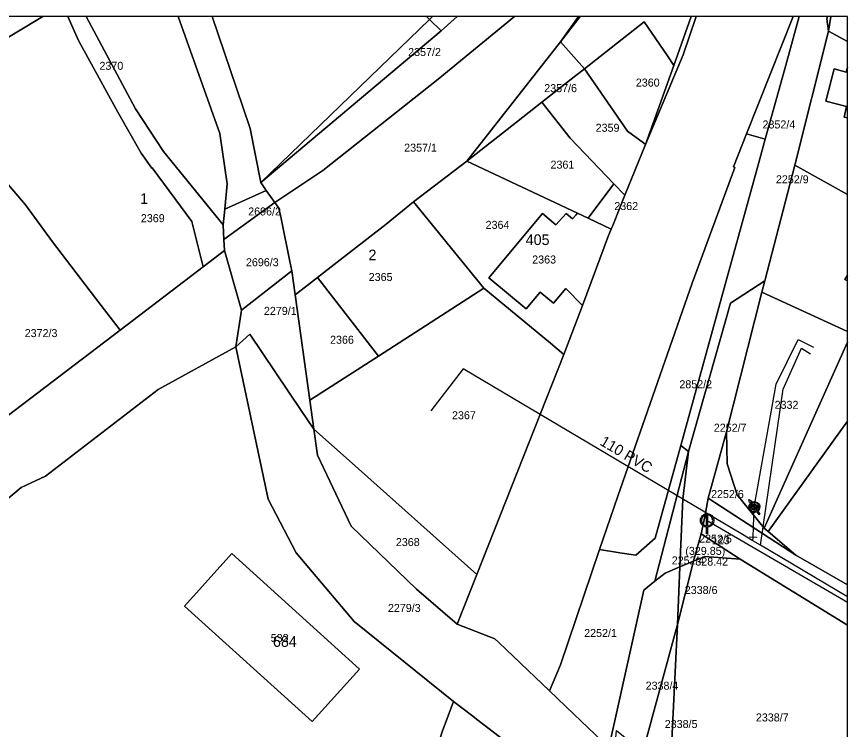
# Model space of a CAD drawing. Extents: x -561316 to -560969, y -1077679 to -1077341.
# Drawn here: x -561124.4 to -560968.7, y -1077474.3 to -1077340.8 of the extents above; entities that cross this region are included whole.
import ezdxf

# ---------------------------------------------------------------- set-up
doc = ezdxf.new("R2010")
doc.units = 0
for name, color, linetype in [('Adresní místo-text', 7, 'Continuous'), ('Armatura vodovodní', 7, 'Continuous'), ('Kanalizační přípojka', 7, 'Continuous'), ('Kanalizační stoka', 7, 'Continuous'), ('Kanalizační šachta', 7, 'Continuous'), ('Odběrné místo', 7, 'Continuous'), ('Parcela-polygon', 7, 'Continuous'), ('Parcela-text', 7, 'Continuous'), ('Popis šachty', 7, 'Continuous'), ('Vodovodní přípojka', 7, 'Continuous'), ('Vodovodní řad', 7, 'Continuous'), ('Řad vodovodní popis', 7, 'Continuous')]:
    doc.layers.add(name, color=color, linetype=linetype)

msp = doc.modelspace()

# ---------------------------------------------------------------- linework, layer by layer
at = {"layer": 'Armatura vodovodní'}
msp.add_lwpolyline([(-560986.98, -1077438.21), (-560985.73, -1077438.26), (-560985.74, -1077438.34), (-560986.99, -1077438.28), (-560986.98, -1077438.21)], dxfattribs=at)
at = {"layer": 'Kanalizační přípojka'}
msp.add_lwpolyline([(-560985, -1077439.77), (-560980.73, -1077410.59), (-560977.27, -1077402.9), (-560975.58, -1077403.92)], dxfattribs=at)
at = {"layer": 'Kanalizační stoka'}
msp.add_line((-560994.97, -1077435.15), (-560968.69, -1077450.45), dxfattribs=at)
at = {"layer": 'Kanalizační šachta'}
for points in [[(-560995.07, -1077436.19), (-560995.07, -1077434.11)], [(-560994.87, -1077434.11), (-560994.87, -1077436.19)], [(-560994.87, -1077436.4), (-560994.87, -1077437.65), (-560995.07, -1077437.65), (-560995.07, -1077436.4)]]:
    msp.add_lwpolyline(points, dxfattribs=at)
for points in [[(-560995.07, -1077436.4), (-560995.33, -1077436.38), (-560995.59, -1077436.23), (-560995.89, -1077436.07), (-560996.06, -1077435.77), (-560996.22, -1077435.47), (-560996.22, -1077435.15), (-560996.22, -1077434.82), (-560996.05, -1077434.52), (-560995.88, -1077434.22), (-560995.59, -1077434.06), (-560995.29, -1077433.9), (-560994.97, -1077433.9), (-560994.66, -1077433.9), (-560994.36, -1077434.06), (-560994.06, -1077434.22), (-560993.89, -1077434.52), (-560993.72, -1077434.82), (-560993.72, -1077435.15), (-560993.72, -1077435.47), (-560993.88, -1077435.77), (-560994.05, -1077436.07), (-560994.35, -1077436.23), (-560994.61, -1077436.38), (-560994.87, -1077436.4)], [(-560995.07, -1077434.11), (-560995.27, -1077434.13), (-560995.49, -1077434.24), (-560995.73, -1077434.38), (-560995.87, -1077434.63), (-560996.01, -1077434.88), (-560996.01, -1077435.15), (-560996.01, -1077435.42), (-560995.88, -1077435.67), (-560995.74, -1077435.91), (-560995.49, -1077436.05), (-560995.28, -1077436.17), (-560995.07, -1077436.19)], [(-560994.87, -1077436.19), (-560994.66, -1077436.17), (-560994.45, -1077436.05), (-560994.2, -1077435.91), (-560994.06, -1077435.67), (-560993.93, -1077435.42), (-560993.93, -1077435.15), (-560993.93, -1077434.88), (-560994.07, -1077434.63), (-560994.21, -1077434.38), (-560994.46, -1077434.24), (-560994.67, -1077434.13), (-560994.87, -1077434.11)]]:
    msp.add_open_spline(points, degree=3, dxfattribs=at)
at = {"layer": 'Odběrné místo'}
for points in [[(-560986.87, -1077431.71), (-560987, -1077431.81), (-560987.14, -1077431.19), (-560986.6, -1077431.51), (-560986.75, -1077431.62), (-560986.65, -1077431.78)], [(-560986.77, -1077431.86), (-560986.87, -1077431.71)], [(-560986.51, -1077432.24), (-560986.67, -1077432)], [(-560986.55, -1077431.91), (-560986.38, -1077432.16)], [(-560985.98, -1077433), (-560986.43, -1077432.34)], [(-560986.3, -1077432.27), (-560985.84, -1077432.93)], [(-560985.72, -1077433.37), (-560985.9, -1077433.12)], [(-560985.76, -1077433.04), (-560985.59, -1077433.29)], [(-560985.49, -1077433.42), (-560985.1, -1077433.99), (-560985.23, -1077434.07), (-560985.62, -1077433.51)]]:
    msp.add_lwpolyline(points, dxfattribs=at)
for points in [[(-560985.62, -1077433.51), (-560985.93, -1077433.7), (-560986.3, -1077433.63), (-560986.72, -1077433.56), (-560986.95, -1077433.22), (-560987.19, -1077432.87), (-560987.12, -1077432.46), (-560987.05, -1077432.09), (-560986.77, -1077431.86)], [(-560986.67, -1077432), (-560986.9, -1077432.19), (-560986.95, -1077432.49), (-560987.02, -1077432.83), (-560986.82, -1077433.12), (-560986.62, -1077433.41), (-560986.27, -1077433.47), (-560985.97, -1077433.52), (-560985.72, -1077433.37)], [(-560985.9, -1077433.12), (-560985.91, -1077433.12), (-560985.93, -1077433.13), (-560986.07, -1077433.17), (-560986.2, -1077433.14), (-560986.47, -1077433.09), (-560986.59, -1077432.93), (-560986.71, -1077432.76), (-560986.68, -1077432.53), (-560986.65, -1077432.39), (-560986.56, -1077432.28), (-560986.54, -1077432.26), (-560986.51, -1077432.24)], [(-560986.65, -1077431.78), (-560986.33, -1077431.58), (-560985.95, -1077431.65), (-560985.54, -1077431.72), (-560985.3, -1077432.06), (-560985.06, -1077432.4), (-560985.14, -1077432.82), (-560985.2, -1077433.19), (-560985.49, -1077433.42)], [(-560986.43, -1077432.34), (-560986.45, -1077432.36), (-560986.47, -1077432.38), (-560986.54, -1077432.45), (-560986.55, -1077432.56), (-560986.58, -1077432.7), (-560986.5, -1077432.83), (-560986.42, -1077432.95), (-560986.18, -1077433), (-560986.07, -1077433.02), (-560985.98, -1077433)], [(-560985.59, -1077433.29), (-560985.36, -1077433.09), (-560985.3, -1077432.79), (-560985.24, -1077432.44), (-560985.44, -1077432.16), (-560985.64, -1077431.87), (-560985.98, -1077431.81), (-560986.29, -1077431.76), (-560986.55, -1077431.91)], [(-560986.38, -1077432.16), (-560986.36, -1077432.15), (-560986.33, -1077432.14), (-560986.19, -1077432.1), (-560986.04, -1077432.13), (-560985.87, -1077432.16), (-560985.76, -1077432.24), (-560985.64, -1077432.33), (-560985.6, -1077432.46), (-560985.56, -1077432.59), (-560985.58, -1077432.73), (-560985.61, -1077432.88), (-560985.7, -1077432.98), (-560985.73, -1077433.02), (-560985.76, -1077433.04)], [(-560985.84, -1077432.93), (-560985.73, -1077432.85), (-560985.7, -1077432.71), (-560985.67, -1077432.55), (-560985.77, -1077432.43), (-560985.86, -1077432.31), (-560986.06, -1077432.27), (-560986.19, -1077432.25), (-560986.3, -1077432.27), (-560986.3, -1077432.27), (-560986.3, -1077432.27)]]:
    msp.add_open_spline(points, degree=3, dxfattribs=at)
at = {"layer": 'Parcela-polygon'}
for p, q in [((-561119.43, -1077340.8), (-561125.97, -1077340.8)), ((-561114.76, -1077340.8), (-561119.43, -1077340.8)), ((-561111.34, -1077340.8), (-561114.76, -1077340.8)), ((-561094.11, -1077340.8), (-561111.34, -1077340.8)), ((-561087.73, -1077340.8), (-561094.11, -1077340.8)), ((-561047.52, -1077340.8), (-561087.73, -1077340.8)), ((-561046.42, -1077340.8), (-561047.52, -1077340.8)), ((-561041.79, -1077340.8), (-561046.42, -1077340.8)), ((-561031.05, -1077340.8), (-561041.79, -1077340.8)), ((-561019.06, -1077340.8), (-561031.05, -1077340.8)), ((-561018.75, -1077340.8), (-561019.06, -1077340.8)), ((-560997.95, -1077340.8), (-561018.75, -1077340.8)), ((-560997.03, -1077340.8), (-560997.95, -1077340.8)), ((-560978.83, -1077340.8), (-560997.03, -1077340.8)), ((-560977.73, -1077340.8), (-560978.83, -1077340.8)), ((-560972.44, -1077340.8), (-560977.73, -1077340.8)), ((-560971.76, -1077340.8), (-560972.44, -1077340.8)), ((-560968.69, -1077341.31), (-560968.69, -1077341.17)), ((-560968.69, -1077345.47), (-560968.69, -1077341.31)), ((-560968.69, -1077350.26), (-560968.69, -1077345.47)), ((-560968.69, -1077359.77), (-560968.69, -1077350.26)), ((-560968.69, -1077374.12), (-560968.69, -1077359.77)), ((-560968.69, -1077389.22), (-560968.69, -1077374.12)), ((-560968.69, -1077390.3), (-560968.69, -1077389.22)), ((-560968.69, -1077399.77), (-560968.69, -1077390.3)), ((-560968.69, -1077401.73), (-560968.69, -1077399.77)), ((-560968.69, -1077416.55), (-560968.69, -1077401.73)), ((-560968.69, -1077447.23), (-560968.69, -1077416.55)), ((-560968.69, -1077454.77), (-560968.69, -1077447.23)), ((-560968.69, -1077494.47), (-560968.69, -1077454.77))]:
    msp.add_line(p, q, dxfattribs=at)
for points in [[(-561119.43, -1077340.8), (-561128.95, -1077346.48), (-561129.16, -1077368.47), (-561126.69, -1077371.36), (-561122.71, -1077376.02), (-561117.62, -1077382.95), (-561109.74, -1077393.26), (-561104.98, -1077399.49), (-561089.39, -1077387.63), (-561091.5, -1077379.14), (-561098.94, -1077369.12), (-561099.03, -1077369.17), (-561101.03, -1077366.35), (-561105.36, -1077358.71), (-561112.78, -1077345.3), (-561114.76, -1077340.8)], [(-561125.97, -1077340.8), (-561128.95, -1077346.48), (-561119.43, -1077340.8)], [(-561114.76, -1077340.8), (-561112.78, -1077345.3), (-561105.36, -1077358.71), (-561101.03, -1077366.35), (-561099.03, -1077369.17), (-561098.94, -1077369.12), (-561091.5, -1077379.14), (-561089.39, -1077387.63), (-561085.41, -1077384.6), (-561085.5, -1077382.55), (-561085.62, -1077379.76), (-561096.82, -1077366.03), (-561102.07, -1077358.07), (-561111.34, -1077340.8)], [(-561111.34, -1077340.8), (-561102.07, -1077358.07), (-561096.82, -1077366.03), (-561085.62, -1077379.76), (-561085.35, -1077376.88), (-561084.91, -1077372.14), (-561086.29, -1077362.67), (-561094.11, -1077340.8)], [(-561094.11, -1077340.8), (-561086.29, -1077362.67), (-561084.91, -1077372.14), (-561085.35, -1077376.88), (-561077.57, -1077373.33), (-561078.62, -1077371.84), (-561080.58, -1077361.77), (-561081.97, -1077357.7), (-561087.73, -1077340.8)], [(-561087.73, -1077340.8), (-561081.97, -1077357.7), (-561080.58, -1077361.77), (-561078.62, -1077371.84), (-561046.97, -1077341.34), (-561047.52, -1077340.8)], [(-561041.79, -1077340.8), (-561044.78, -1077343.48), (-561078.62, -1077371.84), (-561077.57, -1077373.33), (-561075.94, -1077375.61), (-561066.97, -1077369.6), (-561045.36, -1077352.52), (-561031.05, -1077340.8)], [(-561031.05, -1077340.8), (-561045.36, -1077352.52), (-561066.97, -1077369.6), (-561075.94, -1077375.61), (-561075.22, -1077376.64), (-561074.81, -1077378.6), (-561073.15, -1077386.66), (-561072.79, -1077388.42), (-561072.16, -1077392.88), (-561067.97, -1077389.63), (-561064.83, -1077387.2), (-561055.1, -1077379.64), (-561049.99, -1077375.45), (-561039.97, -1077367.88), (-561022.46, -1077345.5), (-561019.06, -1077340.8)], [(-561047.52, -1077340.8), (-561046.97, -1077341.34), (-561046.55, -1077340.93), (-561046.42, -1077340.8)], [(-561046.42, -1077340.8), (-561046.55, -1077340.93), (-561046.97, -1077341.34), (-561044.78, -1077343.48), (-561041.79, -1077340.8)], [(-560997.03, -1077340.8), (-560999.44, -1077347.94), (-561006.51, -1077364.73), (-561010.37, -1077374.26), (-561012.54, -1077379.61), (-561012.94, -1077380.59), (-561013.42, -1077381.77), (-561018.34, -1077394.88), (-561021.79, -1077404.06), (-561038.11, -1077445.26), (-561041.8, -1077454.56), (-561034.74, -1077457.28), (-561034.02, -1077457.97), (-561024.53, -1077467.03), (-561022.46, -1077462.15), (-561015.12, -1077440.58), (-561011.71, -1077430.57), (-560997.76, -1077390.7), (-560989.77, -1077369.06), (-560990.03, -1077368.91), (-560987.57, -1077362.74), (-560978.83, -1077340.8)], [(-561018.75, -1077340.8), (-561022.46, -1077345.5), (-561017.93, -1077350.55), (-561006.76, -1077341.79), (-561002.42, -1077348.16), (-561001.21, -1077349.92), (-560997.95, -1077340.8)], [(-561019.06, -1077340.8), (-561022.46, -1077345.5), (-561018.75, -1077340.8)], [(-560997.95, -1077340.8), (-561001.21, -1077349.92), (-561004.22, -1077358.32), (-561006.51, -1077364.73), (-560999.44, -1077347.94), (-560997.03, -1077340.8)], [(-560977.73, -1077340.8), (-560980.43, -1077350.55), (-560984.08, -1077363.76), (-560985.29, -1077368.14), (-560991.09, -1077389.15), (-560999.92, -1077421.13), (-560998.49, -1077422.25), (-560990.56, -1077394.45), (-560984.15, -1077390.27), (-560978.54, -1077368.63), (-560972.22, -1077343.5), (-560972.51, -1077341.19), (-560972.44, -1077340.8)], [(-560978.83, -1077340.8), (-560987.57, -1077362.74), (-560984.08, -1077363.76), (-560980.43, -1077350.55), (-560977.73, -1077340.8)], [(-560972.44, -1077340.8), (-560972.51, -1077341.19), (-560972.22, -1077343.5), (-560971.76, -1077340.8)], [(-560971.76, -1077340.8), (-560972.22, -1077343.5), (-560968.69, -1077345.47)], [(-560968.69, -1077341.17), (-560968.69, -1077340.8), (-560971.76, -1077340.8)], [(-560968.69, -1077341.17), (-560968.75, -1077341.28), (-560968.69, -1077341.31)], [(-560968.69, -1077341.31), (-560968.75, -1077341.28), (-560968.69, -1077341.17)], [(-560968.69, -1077345.47), (-560972.22, -1077343.5), (-560978.54, -1077368.63), (-560968.69, -1077374.12)], [(-560968.69, -1077350.26), (-560968.92, -1077351.17), (-560971.19, -1077350.59), (-560972.74, -1077356.63), (-560968.85, -1077357.62), (-560969.28, -1077359.62), (-560968.69, -1077359.77)], [(-560968.69, -1077359.77), (-560969.28, -1077359.62), (-560968.85, -1077357.62), (-560972.74, -1077356.63), (-560971.19, -1077350.59), (-560968.92, -1077351.17), (-560968.69, -1077350.26)], [(-560968.69, -1077374.12), (-560978.54, -1077368.63), (-560984.15, -1077390.27), (-560984.71, -1077392.42), (-560968.69, -1077399.77)], [(-561141.46, -1077444.02), (-561123.47, -1077428.97), (-561118.92, -1077426.82), (-561097.85, -1077410.62), (-561083.3, -1077402.66), (-561082.24, -1077395.75), (-561082.73, -1077394.02), (-561085.16, -1077385.46), (-561085.41, -1077384.6), (-561089.39, -1077387.63), (-561104.98, -1077399.49), (-561136.14, -1077423.19)], [(-560968.69, -1077390.3), (-560969.15, -1077390.04), (-560968.69, -1077389.22)], [(-560968.69, -1077389.22), (-560969.15, -1077390.04), (-560968.69, -1077390.3)], [(-560968.69, -1077399.77), (-560984.71, -1077392.42), (-560991.33, -1077418.53), (-560991.23, -1077424.52), (-560989.34, -1077430.33), (-560984.3, -1077436.58), (-560968.69, -1077401.73)], [(-560968.69, -1077401.73), (-560984.3, -1077436.58), (-560983.54, -1077437.22), (-560968.69, -1077416.55)], [(-561091.55, -1077679.32), (-561089.7, -1077665.29), (-561074.75, -1077568.98), (-561063.6, -1077534.48), (-561053.67, -1077503.25), (-561050.47, -1077493.22), (-561048.31, -1077486.41), (-561044.6, -1077474.75), (-561042.48, -1077469.05), (-561061.08, -1077454.04), (-561071.96, -1077441.19), (-561077.2, -1077431.15), (-561083.3, -1077402.66), (-561097.85, -1077410.62), (-561118.92, -1077426.82), (-561123.47, -1077428.97), (-561141.46, -1077444.02)], [(-560968.69, -1077416.55), (-560983.54, -1077437.22), (-560978.33, -1077441.62), (-560968.69, -1077447.23)], [(-560968.69, -1077447.23), (-560978.33, -1077441.62), (-560994.78, -1077430.99), (-560995.41, -1077434.44), (-560996.11, -1077437.68), (-560988.77, -1077442.39), (-560968.69, -1077454.77)], [(-561084.02, -1077441.36), (-561060.11, -1077463.02), (-561069, -1077472.82), (-561092.91, -1077451.18), (-561084.02, -1077441.36)], [(-560968.69, -1077454.77), (-560988.77, -1077442.39), (-560995.41, -1077441.87), (-560997.54, -1077442.76), (-561000.5, -1077454.6), (-561001.87, -1077482.65), (-560982.23, -1077498.52), (-560972.64, -1077506.26), (-560968.69, -1077494.47)]]:
    msp.add_lwpolyline(points, dxfattribs=at)
for points in [[(-561046.97, -1077341.34), (-561078.62, -1077371.84), (-561044.78, -1077343.48)], [(-561017.93, -1077350.55), (-561009.88, -1077362.22), (-561006.88, -1077364.43), (-561006.51, -1077364.73), (-561004.22, -1077358.32), (-561001.21, -1077349.92), (-561002.42, -1077348.16), (-561006.76, -1077341.79)], [(-561022.46, -1077345.5), (-561039.97, -1077367.88), (-561030.7, -1077360.56), (-561025.91, -1077356.81), (-561020.45, -1077352.53), (-561017.93, -1077350.55)], [(-561009.88, -1077362.22), (-561017.93, -1077350.55), (-561020.45, -1077352.53), (-561025.91, -1077356.81), (-561020.64, -1077363.57), (-561012.45, -1077372.09), (-561010.37, -1077374.26), (-561006.51, -1077364.73), (-561006.88, -1077364.43)], [(-561020.64, -1077363.57), (-561025.91, -1077356.81), (-561030.7, -1077360.56), (-561039.97, -1077367.88), (-561019.28, -1077377.61), (-561017.29, -1077378.55), (-561012.45, -1077372.09)], [(-560990.03, -1077368.91), (-560989.77, -1077369.06), (-560997.76, -1077390.7), (-561011.71, -1077430.57), (-561015.12, -1077440.58), (-561011.3, -1077441.2), (-561008.32, -1077441.67), (-561004.7, -1077438.43), (-560999.92, -1077421.13), (-560991.09, -1077389.15), (-560985.29, -1077368.14), (-560984.08, -1077363.76), (-560987.57, -1077362.74)], [(-561035.88, -1077389.73), (-561025.84, -1077377.68), (-561023.31, -1077379.79), (-561021.37, -1077377.65), (-561020.18, -1077378.69), (-561019.57, -1077377.96), (-561019.28, -1077377.61), (-561039.97, -1077367.88), (-561049.99, -1077375.45), (-561036.79, -1077391.63), (-561024.33, -1077401.95), (-561021.79, -1077404.06), (-561018.34, -1077394.88), (-561021.46, -1077391.68), (-561023.74, -1077394.46), (-561026.23, -1077392.37), (-561028.9, -1077395.54)], [(-561148.69, -1077436.73), (-561136.14, -1077423.19), (-561104.98, -1077399.49), (-561109.74, -1077393.26), (-561117.62, -1077382.95), (-561122.71, -1077376.02), (-561126.69, -1077371.36)], [(-561012.45, -1077372.09), (-561017.29, -1077378.55), (-561012.94, -1077380.59), (-561012.54, -1077379.61), (-561010.37, -1077374.26)], [(-561077.57, -1077373.33), (-561085.35, -1077376.88), (-561085.62, -1077379.76), (-561085.5, -1077382.55), (-561075.94, -1077375.61)], [(-561074.81, -1077378.6), (-561075.22, -1077376.64), (-561075.94, -1077375.61), (-561085.5, -1077382.55), (-561085.41, -1077384.6), (-561085.16, -1077385.46), (-561082.73, -1077394.02), (-561082.24, -1077395.75), (-561072.79, -1077388.42), (-561073.15, -1077386.66)], [(-561067.97, -1077389.63), (-561061.48, -1077397.99), (-561056.55, -1077404.35), (-561036.79, -1077391.63), (-561049.99, -1077375.45), (-561055.1, -1077379.64), (-561064.83, -1077387.2)], [(-561025.84, -1077377.68), (-561035.88, -1077389.73), (-561028.9, -1077395.54), (-561026.23, -1077392.37), (-561023.74, -1077394.46), (-561021.46, -1077391.68), (-561018.34, -1077394.88), (-561013.42, -1077381.77), (-561012.94, -1077380.59), (-561017.29, -1077378.55), (-561019.28, -1077377.61), (-561019.57, -1077377.96), (-561020.18, -1077378.69), (-561021.37, -1077377.65), (-561023.31, -1077379.79)], [(-561072.79, -1077388.42), (-561082.24, -1077395.75), (-561083.3, -1077402.66), (-561080.63, -1077400.23), (-561071.01, -1077414.57), (-561068.64, -1077418.05), (-561069.4, -1077412.62), (-561072.16, -1077392.88)], [(-561072.16, -1077392.88), (-561069.4, -1077412.62), (-561056.55, -1077404.35), (-561061.48, -1077397.99), (-561067.97, -1077389.63)], [(-560990.56, -1077394.45), (-560998.49, -1077422.25), (-560999.52, -1077431.13), (-561000.11, -1077443.84), (-560997.54, -1077442.76), (-560996.11, -1077437.68), (-560995.41, -1077434.44), (-560994.78, -1077430.99), (-560991.33, -1077418.53), (-560984.71, -1077392.42), (-560984.15, -1077390.27)], [(-561024.33, -1077401.95), (-561036.79, -1077391.63), (-561056.55, -1077404.35), (-561069.4, -1077412.62), (-561068.64, -1077418.05), (-561062.05, -1077423.93), (-561038.11, -1077445.26), (-561021.79, -1077404.06)], [(-561049.4, -1077448.02), (-561061.67, -1077436.19), (-561067.96, -1077422.91), (-561068.64, -1077418.05), (-561071.01, -1077414.57), (-561080.63, -1077400.23), (-561083.3, -1077402.66), (-561077.2, -1077431.15), (-561071.96, -1077441.19), (-561061.08, -1077454.04), (-561042.48, -1077469.05), (-561038.9, -1077471.78), (-561038.17, -1077472.34), (-561027.8, -1077480.27), (-561023.49, -1077483.56), (-561015.97, -1077489.32), (-561013.39, -1077477.66), (-561019.96, -1077471.39), (-561024.53, -1077467.03), (-561034.02, -1077457.97), (-561034.74, -1077457.28), (-561041.8, -1077454.56)], [(-561068.64, -1077418.05), (-561067.96, -1077422.91), (-561061.67, -1077436.19), (-561049.4, -1077448.02), (-561041.8, -1077454.56), (-561038.11, -1077445.26), (-561062.05, -1077423.93)], [(-560994.78, -1077430.99), (-560978.33, -1077441.62), (-560983.54, -1077437.22), (-560984.3, -1077436.58), (-560989.34, -1077430.33), (-560991.23, -1077424.52), (-560991.33, -1077418.53)], [(-560999.92, -1077421.13), (-561004.7, -1077438.43), (-561008.32, -1077441.67), (-561011.3, -1077441.2), (-561015.12, -1077440.58), (-561022.46, -1077462.15), (-561024.53, -1077467.03), (-561019.96, -1077471.39), (-561013.39, -1077477.66), (-561011.59, -1077469.52), (-561006.86, -1077448.2), (-561004.74, -1077446.51), (-560998.49, -1077422.25)], [(-561004.74, -1077446.51), (-561002.84, -1077444.99), (-561000.11, -1077443.84), (-560999.52, -1077431.13), (-560998.49, -1077422.25)], [(-560996.11, -1077437.68), (-560997.54, -1077442.76), (-560995.41, -1077441.87), (-560988.77, -1077442.39)], [(-561092.91, -1077451.18), (-561069, -1077472.82), (-561060.11, -1077463.02), (-561084.02, -1077441.36)], [(-561000.5, -1077454.6), (-560997.54, -1077442.76), (-561000.11, -1077443.84)], [(-561002.84, -1077444.99), (-561004.74, -1077446.51), (-561006.86, -1077448.2), (-561011.59, -1077469.52), (-561013.39, -1077477.66), (-561012.31, -1077478.48), (-561011.96, -1077474.5), (-561007.03, -1077478.49), (-561000.5, -1077454.6), (-561000.11, -1077443.84)], [(-561007.03, -1077478.49), (-561001.87, -1077482.65), (-561000.5, -1077454.6)], [(-561042.48, -1077469.05), (-561044.6, -1077474.75), (-561048.31, -1077486.41), (-561043.17, -1077489.63), (-561034.56, -1077495.01), (-561029.82, -1077484.67), (-561027.8, -1077480.27), (-561038.17, -1077472.34), (-561038.9, -1077471.78)]]:
    msp.add_lwpolyline(points, close=True, dxfattribs=at)
at = {"layer": 'Vodovodní přípojka'}
for points in [[(-560986.13, -1077432.64), (-560982.02, -1077409.61), (-560977.88, -1077401.24), (-560975.01, -1077402.68)], [(-560986.39, -1077438.94), (-560986.36, -1077438.27), (-560986.13, -1077432.64)]]:
    msp.add_lwpolyline(points, dxfattribs=at)
at = {"layer": 'Vodovodní řad'}
msp.add_lwpolyline([(-560968.69, -1077449.44), (-560985, -1077439.77), (-560986.39, -1077438.94), (-560988.35, -1077437.78), (-561040.68, -1077406.77), (-561046.77, -1077414.63)], dxfattribs=at)

# ---------------------------------------------------------------- texts
at = {"layer": 'Adresní místo-text'}
for s, p in [('1', (-561101.19, -1077375.87)), ('405', (-561028.96, -1077383.57)), ('2', (-561058.42, -1077386.43)), ('684', (-561076.32, -1077458.81))]:
    msp.add_text(s, height=2, dxfattribs=at).set_placement(p)
at = {"layer": 'Parcela-text'}
for s, p in [('2357/2', (-561050.99, -1077348.18)), ('2370', (-561108.83, -1077350.76)), ('2357/6', (-561025.49, -1077354.94)), ('2360', (-561008.33, -1077353.9)), ('2359', (-561015.86, -1077362.36)), ('2852/4', (-560984.59, -1077361.74)), ('2357/1', (-561051.73, -1077366.09)), ('2361', (-561024.31, -1077369.27)), ('2252/9', (-560982.08, -1077372.01)), ('2696/2', (-561080.96, -1077378.03)), ('2362', (-561012.36, -1077377.02)), ('2369', (-561101.07, -1077379.29)), ('2364', (-561036.47, -1077380.54)), ('2696/3', (-561081.38, -1077387.54)), ('2363', (-561027.74, -1077387.03)), ('2365', (-561058.38, -1077390.3)), ('2279/1', (-561078.01, -1077396.65)), ('2372/3', (-561122.84, -1077400.81)), ('2366', (-561065.62, -1077402.06)), ('2852/2', (-561000.17, -1077410.39)), ('2332', (-560982.32, -1077414.24)), ('2367', (-561042.77, -1077416.19)), ('2252/7', (-560993.72, -1077418.53)), ('2252/6', (-560994.23, -1077430.95)), ('2368', (-561053.29, -1077439.94)), ('2252/5', (-560996.47, -1077439.31)), ('2252/4', (-561001.6, -1077443.38)), ('2338/6', (-560999.16, -1077448.92)), ('2279/3', (-561054.78, -1077452.28)), ('2252/1', (-561018.01, -1077456.97)), ('532', (-561076.74, -1077457.9)), ('2338/4', (-561006.49, -1077466.83)), ('2338/7', (-560985.83, -1077472.78)), ('2338/5', (-561002.91, -1077474.01))]:
    msp.add_text(s, height=1.5, dxfattribs=at).set_placement(p)
at = {"layer": 'Popis šachty'}
for s, p in [('123', (-560994.08, -1077439.59)), ('(329.85)', (-560999.05, -1077441.59)), ('328.42', (-560997.18, -1077443.59))]:
    msp.add_text(s, height=1.5, dxfattribs=at).set_placement(p)
at = {"layer": 'Řad vodovodní popis'}
msp.add_text(' 110 PVC', height=2, rotation=329.3428, dxfattribs=at).set_placement((-561015.85, -1077420.52))

doc.saveas('drawing.dxf')
